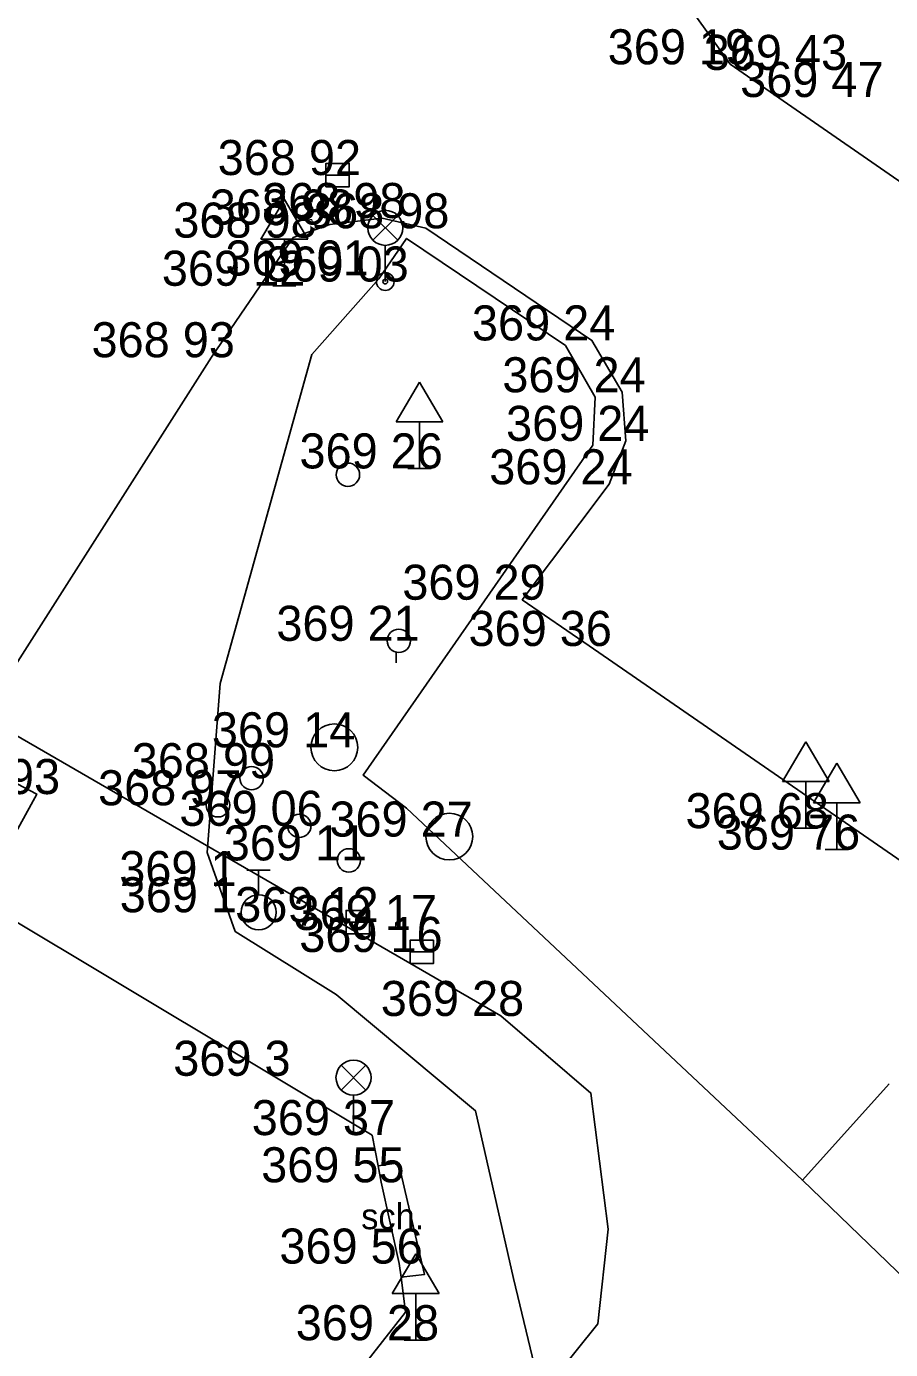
# Model space of a CAD drawing. Extents: x -688316 to -688024, y -973785 to -973591.
# Drawn here: x -688108.72 to -688090.23, y -973719.16 to -973690.84 of the extents above; entities that cross this region are included whole.
import ezdxf

# ---------------------------------------------------------------- set-up
doc = ezdxf.new("R2010")
doc.units = 0
for name, color, linetype in [('KAM_HELP', 7, 'Continuous'), ('Vrstva 10', 7, 'Continuous'), ('Vrstva 11', 7, 'Continuous'), ('Vrstva 27', 7, 'Continuous'), ('Vrstva 28_Verejne osvetleni', 7, 'Continuous'), ('Vrstva 3', 7, 'Continuous'), ('Vrstva 31', 7, 'Continuous'), ('Vrstva 33', 7, 'Continuous'), ('Vrstva 34', 7, 'Continuous'), ('Vrstva 41', 7, 'Continuous'), ('Vrstva 5', 7, 'Continuous'), ('Vrstva 6', 7, 'Continuous')]:
    doc.layers.add(name, color=color, linetype=linetype)

# ---------------------------------------------------------------- blocks, each defined once
blk = doc.blocks.new('DZ')
at = {"layer": 'Vrstva 34'}
for p, q in [((-5, 10), (0, 18.5)), ((0, 18.5), (5, 10)), ((-5, 10), (5, 10)), ((0, 0), (0, 10)), ((-2.49, 0), (2.49, 0))]:
    blk.add_line(p, q, dxfattribs=at)
blk = doc.blocks.new('SAK')
at = {"layer": 'Vrstva 27'}
blk.add_circle((0, 0), 5, dxfattribs=at)
blk = doc.blocks.new('VP')
at = {"layer": 'Vrstva 27'}
blk.add_line((-2.5, 0), (2.5, 0), dxfattribs=at)
blk.add_lwpolyline([(-2.5, -2.5), (2.5, -2.5), (2.5, 2.5), (-2.5, 2.5)], close=True, dxfattribs=at)
blk = doc.blocks.new('SV')
at = {"layer": 'Vrstva 28_Verejne osvetleni'}
blk.add_circle((0, 0), 2.5, dxfattribs=at)
blk = doc.blocks.new('SP')
at = {"layer": 'Vrstva 31'}
blk.add_circle((0, 0), 2.5, dxfattribs=at)
blk = doc.blocks.new('LA')
at = {"layer": 'Vrstva 33'}
for p, q in [((-2.65, 14.15), (2.65, 8.85)), ((-2.65, 8.85), (2.65, 14.15)), ((0, 0), (0, 7.75))]:
    blk.add_line(p, q, dxfattribs=at)
for centre, radius in [((0, 11.5), 3.75), ((0, 0), 1.9), ((0, 0), 0.5)]:
    blk.add_circle(centre, radius, dxfattribs=at)
blk = doc.blocks.new('HYN')
at = {"layer": 'Vrstva 28_Verejne osvetleni'}
for p, q in [((-2.5, 8.99), (2.5, 8.99)), ((0, 3.75), (0, 8.99))]:
    blk.add_line(p, q, dxfattribs=at)
blk.add_circle((0, 0), 3.75, dxfattribs=at)
blk = doc.blocks.new('LAO')
at = {"layer": 'Vrstva 33'}
for p, q in [((-2.65, 14.16), (2.65, 8.85)), ((-2.65, 8.85), (2.65, 14.16)), ((0, 0), (0, 7.75))]:
    blk.add_line(p, q, dxfattribs=at)
blk.add_circle((0, 11.5), 3.75, dxfattribs=at)
blk = doc.blocks.new('SKSCH0')
at = {"layer": 'Vrstva 41'}
blk.add_text('sch.', height=5.5, dxfattribs=at).set_placement((-8.15, -3.04))

msp = doc.modelspace()

# ---------------------------------------------------------------- linework, layer by layer
at = {"layer": 'KAM_HELP'}
msp.add_line((-688100.804, -973704.239), (-688100.804, -973704.461), dxfattribs=at)
at = {"layer": 'Vrstva 10'}
for p, q in [((-688093.66, -973691.65), (-688072.24, -973706.48)), ((-688103.01, -973695.36), (-688104.76, -973697.92)), ((-688104.76, -973697.92), (-688109.65, -973705.6)), ((-688077.23, -973717.52), (-688096.68, -973704.1)), ((-688098.57, -973712.02), (-688109.65, -973705.6)), ((-688117.48, -973744.56), (-688096.49, -973718.61))]:
    msp.add_line(p, q, dxfattribs=at)
for points in [[(-688093.66, -973691.65), (-688094.86, -973689.96), (-688094.89, -973687.94), (-688093.92, -973685.52), (-688092.54, -973682.87)], [(-688103.01, -973695.36), (-688102.23, -973695.08), (-688101.11, -973694.94), (-688100.17, -973695.16), (-688096.62, -973697.56), (-688095.97, -973698.67), (-688095.89, -973699.71), (-688096.25, -973700.64), (-688098.11, -973703.11), (-688096.68, -973704.1)], [(-688109.87, -973706.55), (-688108.5, -973707.27), (-688108.98, -973708.16), (-688110.34, -973707.43), (-688109.87, -973706.55)], [(-688096.49, -973718.61), (-688096.27, -973716.58), (-688096.64, -973713.67), (-688098.57, -973712.02)]]:
    msp.add_lwpolyline(points, dxfattribs=at)
at = {"layer": 'Vrstva 11'}
msp.add_lwpolyline([(-688101.19, -973715.23), (-688100.76, -973715.16), (-688100.2, -973717.55), (-688100.7, -973717.61)], dxfattribs=at)
at = {"layer": 'Vrstva 3'}
for points in [[(-688092.114, -973715.537), (-688100.586, -973707.573), (-688101.51, -973706.867), (-688096.596, -973699.801), (-688096.549, -973698.771), (-688097.183, -973697.669), (-688100.586, -973695.375), (-688101.18, -973696.24)], [(-688092.114, -973715.537), (-688100.586, -973707.573), (-688101.51, -973706.867), (-688096.596, -973699.801), (-688096.549, -973698.771), (-688097.183, -973697.669), (-688100.586, -973695.375), (-688101.18, -973696.24)], [(-688092.114, -973715.537), (-688100.586, -973707.573), (-688101.51, -973706.867), (-688096.596, -973699.801), (-688096.549, -973698.771), (-688097.183, -973697.669), (-688100.586, -973695.375), (-688101.18, -973696.24)], [(-688092.114, -973715.537), (-688100.586, -973707.573), (-688101.51, -973706.867), (-688096.596, -973699.801), (-688096.549, -973698.771), (-688097.183, -973697.669), (-688100.586, -973695.375), (-688101.18, -973696.24)], [(-688102.09, -973711.56), (-688104.25, -973710.21), (-688104.85, -973708.52), (-688104.57, -973704.9), (-688102.61, -973697.86), (-688101.18, -973696.24)], [(-688102.09, -973711.56), (-688104.25, -973710.21), (-688104.85, -973708.52), (-688104.57, -973704.9), (-688102.61, -973697.86), (-688101.18, -973696.24)], [(-688102.09, -973711.56), (-688104.25, -973710.21), (-688104.85, -973708.52), (-688104.57, -973704.9), (-688102.61, -973697.86), (-688101.18, -973696.24)], [(-688102.09, -973711.56), (-688104.25, -973710.21), (-688104.85, -973708.52), (-688104.57, -973704.9), (-688102.61, -973697.86), (-688101.18, -973696.24)], [(-688094.03, -973728.25), (-688096.82, -973723.78), (-688098.3, -973717.64), (-688099.11, -973714.05), (-688102.09, -973711.56)], [(-688094.03, -973728.25), (-688096.82, -973723.78), (-688098.3, -973717.64), (-688099.11, -973714.05), (-688102.09, -973711.56)], [(-688094.03, -973728.25), (-688096.82, -973723.78), (-688098.3, -973717.64), (-688099.11, -973714.05), (-688102.09, -973711.56)], [(-688094.03, -973728.25), (-688096.82, -973723.78), (-688098.3, -973717.64), (-688099.11, -973714.05), (-688102.09, -973711.56)], [(-688071.97, -973725.53), (-688075.592, -973732.953), (-688087.068, -973720.398), (-688092.114, -973715.537), (-688090.26, -973713.47)], [(-688071.97, -973725.53), (-688075.592, -973732.953), (-688087.068, -973720.398), (-688092.114, -973715.537), (-688090.26, -973713.47)], [(-688071.97, -973725.53), (-688075.592, -973732.953), (-688087.068, -973720.398), (-688092.114, -973715.537), (-688090.26, -973713.47)], [(-688071.97, -973725.53), (-688075.592, -973732.953), (-688087.068, -973720.398), (-688092.114, -973715.537), (-688090.26, -973713.47)]]:
    msp.add_lwpolyline(points, dxfattribs=at)
at = {"layer": 'Vrstva 5'}
msp.add_line((-688101.32, -973714.57), (-688115.6, -973706.01), dxfattribs=at)
for points in [[(-688101.32, -973714.57), (-688101.19, -973715.23), (-688101.13, -973715.58)], [(-688100.74, -973717.32), (-688100.7, -973717.61), (-688100.61, -973718.36), (-688104.1, -973722.82), (-688104.28, -973723.02), (-688104.45, -973723.22), (-688117.23, -973738.61)]]:
    msp.add_lwpolyline(points, dxfattribs=at)
at = {"layer": 'Vrstva 6'}
msp.add_line((-688101.13, -973715.58), (-688100.74, -973717.32), dxfattribs=at)

# ---------------------------------------------------------------- block references
at = {"layer": 'Vrstva 27', "xscale": 0.1, "yscale": 0.10000000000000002}
for name, p in [('VP', (-688102.06, -973694.02)), ('SAK', (-688102.13, -973706.27)), ('SAK', (-688099.67, -973708.18)), ('VP', (-688101.63, -973710.01)), ('VP', (-688100.26, -973710.65))]:
    msp.add_blockref(name, p, dxfattribs=at)
at = {"layer": 'Vrstva 28_Verejne osvetleni', "xscale": 0.1, "yscale": 0.10000000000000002}
for name, p in [('SV', (-688103.9, -973706.93)), ('SV', (-688104.62, -973707.51)), ('SV', (-688102.88, -973707.95)), ('SV', (-688101.82, -973708.69)), ('HYN', (-688103.75, -973709.8))]:
    msp.add_blockref(name, p, dxfattribs=at)
at = {"layer": 'Vrstva 31', "xscale": 0.1, "yscale": 0.10000000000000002}
for p in [(-688101.84, -973700.435), (-688100.75, -973703.99)]:
    msp.add_blockref('SP', p, dxfattribs=at)
at = {"layer": 'Vrstva 33', "xscale": 0.1, "yscale": 0.10000000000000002}
for name, p in [('LA', (-688101.04, -973696.3)), ('LAO', (-688101.72, -973714.49))]:
    msp.add_blockref(name, p, dxfattribs=at)
at = {"layer": 'Vrstva 34', "xscale": 0.1, "yscale": 0.10000000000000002}
for p in [(-688103.2, -973696.39), (-688103.2, -973696.39), (-688103.2, -973696.39), (-688103.2, -973696.39), (-688100.31, -973700.3), (-688100.31, -973700.3), (-688100.31, -973700.3), (-688100.31, -973700.3), (-688092.04, -973708), (-688092.04, -973708), (-688092.04, -973708), (-688092.04, -973708), (-688091.38, -973708.46), (-688091.38, -973708.46), (-688091.38, -973708.46), (-688091.38, -973708.46), (-688100.39, -973718.96), (-688100.39, -973718.96), (-688100.39, -973718.96), (-688100.39, -973718.96)]:
    msp.add_blockref('DZ', p, dxfattribs=at)
at = {"layer": 'Vrstva 41', "xscale": 0.1, "yscale": 0.10000000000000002}
msp.add_blockref('SKSCH0', (-688100.74, -973716.28), dxfattribs=at)

# ---------------------------------------------------------------- texts
at = {"layer": 'Vrstva 3'}
for s, p in [('369 19 ', (-688096.281, -973691.65)), ('369 19 ', (-688096.281, -973691.65)), ('369 19 ', (-688096.281, -973691.65)), ('369 19 ', (-688096.281, -973691.65)), ('369 19 ', (-688096.281, -973691.65)), ('369 19 ', (-688096.281, -973691.65)), ('369 19 ', (-688096.281, -973691.65)), ('369 43 ', (-688094.226, -973691.77)), ('369 43 ', (-688094.226, -973691.77)), ('369 43 ', (-688094.226, -973691.77)), ('369 43 ', (-688094.226, -973691.77)), ('369 43 ', (-688094.226, -973691.77)), ('369 43 ', (-688094.226, -973691.77)), ('369 43 ', (-688094.226, -973691.77)), ('369 47 ', (-688093.446, -973692.35)), ('369 47 ', (-688093.446, -973692.35)), ('369 47 ', (-688093.446, -973692.35)), ('369 47 ', (-688093.446, -973692.35)), ('369 47 ', (-688093.446, -973692.35)), ('369 47 ', (-688093.446, -973692.35)), ('369 47 ', (-688093.446, -973692.35)), ('368 92 ', (-688104.626, -973694.02)), ('368 92 ', (-688104.626, -973694.02)), ('368 92 ', (-688104.626, -973694.02)), ('368 92 ', (-688104.626, -973694.02)), ('368 92 ', (-688104.626, -973694.02)), ('368 92 ', (-688104.626, -973694.02)), ('368 92 ', (-688104.626, -973694.02)), ('368 98 ', (-688103.676, -973694.94)), ('368 98 ', (-688103.676, -973694.94)), ('368 98 ', (-688103.676, -973694.94)), ('368 98 ', (-688103.676, -973694.94)), ('368 98 ', (-688103.676, -973694.94)), ('368 98 ', (-688103.676, -973694.94)), ('368 98 ', (-688103.676, -973694.94)), ('368 98 ', (-688104.796, -973695.08)), ('368 98 ', (-688104.796, -973695.08)), ('368 98 ', (-688104.796, -973695.08)), ('368 98 ', (-688104.796, -973695.08)), ('368 98 ', (-688104.796, -973695.08)), ('368 98 ', (-688104.796, -973695.08)), ('368 98 ', (-688104.796, -973695.08)), ('368 98 ', (-688102.736, -973695.16)), ('368 98 ', (-688102.736, -973695.16)), ('368 98 ', (-688102.736, -973695.16)), ('368 98 ', (-688102.736, -973695.16)), ('368 98 ', (-688102.736, -973695.16)), ('368 98 ', (-688102.736, -973695.16)), ('368 98 ', (-688102.736, -973695.16)), ('368 98 ', (-688105.576, -973695.36)), ('368 98 ', (-688105.576, -973695.36)), ('368 98 ', (-688105.576, -973695.36)), ('368 98 ', (-688105.576, -973695.36)), ('368 98 ', (-688105.576, -973695.36)), ('368 98 ', (-688105.576, -973695.36)), ('368 98 ', (-688105.576, -973695.36)), ('369 12 ', (-688105.821, -973696.39)), ('369 12 ', (-688105.821, -973696.39)), ('369 12 ', (-688105.821, -973696.39)), ('369 12 ', (-688105.821, -973696.39)), ('369 12 ', (-688105.821, -973696.39)), ('369 12 ', (-688105.821, -973696.39)), ('369 12 ', (-688105.821, -973696.39)), ('369 01 ', (-688104.461, -973696.17)), ('369 01 ', (-688104.461, -973696.17)), ('369 01 ', (-688104.461, -973696.17)), ('369 01 ', (-688104.461, -973696.17)), ('369 01 ', (-688104.461, -973696.17)), ('369 01 ', (-688104.461, -973696.17)), ('369 01 ', (-688104.461, -973696.17)), ('369 03 ', (-688103.606, -973696.3)), ('369 03 ', (-688103.606, -973696.3)), ('369 03 ', (-688103.606, -973696.3)), ('369 03 ', (-688103.606, -973696.3)), ('369 03 ', (-688103.606, -973696.3)), ('369 03 ', (-688103.606, -973696.3)), ('369 03 ', (-688103.606, -973696.3)), ('369 24 ', (-688099.186, -973697.56)), ('369 24 ', (-688099.186, -973697.56)), ('369 24 ', (-688099.186, -973697.56)), ('369 24 ', (-688099.186, -973697.56)), ('369 24 ', (-688099.186, -973697.56)), ('369 24 ', (-688099.186, -973697.56)), ('369 24 ', (-688099.186, -973697.56)), ('368 93 ', (-688107.326, -973697.92)), ('368 93 ', (-688107.326, -973697.92)), ('368 93 ', (-688107.326, -973697.92)), ('368 93 ', (-688107.326, -973697.92)), ('368 93 ', (-688107.326, -973697.92)), ('368 93 ', (-688107.326, -973697.92)), ('368 93 ', (-688107.326, -973697.92)), ('369 24 ', (-688098.536, -973698.67)), ('369 24 ', (-688098.536, -973698.67)), ('369 24 ', (-688098.536, -973698.67)), ('369 24 ', (-688098.536, -973698.67)), ('369 24 ', (-688098.536, -973698.67)), ('369 24 ', (-688098.536, -973698.67)), ('369 24 ', (-688098.536, -973698.67)), ('369 24 ', (-688098.456, -973699.71)), ('369 24 ', (-688098.456, -973699.71)), ('369 24 ', (-688098.456, -973699.71)), ('369 24 ', (-688098.456, -973699.71)), ('369 24 ', (-688098.456, -973699.71)), ('369 24 ', (-688098.456, -973699.71)), ('369 24 ', (-688098.456, -973699.71)), ('369 26 ', (-688102.876, -973700.3)), ('369 26 ', (-688102.876, -973700.3)), ('369 26 ', (-688102.876, -973700.3)), ('369 26 ', (-688102.876, -973700.3)), ('369 26 ', (-688102.876, -973700.3)), ('369 26 ', (-688102.876, -973700.3)), ('369 26 ', (-688102.876, -973700.3)), ('369 24 ', (-688098.816, -973700.64)), ('369 24 ', (-688098.816, -973700.64)), ('369 24 ', (-688098.816, -973700.64)), ('369 24 ', (-688098.816, -973700.64)), ('369 24 ', (-688098.816, -973700.64)), ('369 24 ', (-688098.816, -973700.64)), ('369 24 ', (-688098.816, -973700.64)), ('369 29 ', (-688100.676, -973703.11)), ('369 29 ', (-688100.676, -973703.11)), ('369 29 ', (-688100.676, -973703.11)), ('369 29 ', (-688100.676, -973703.11)), ('369 29 ', (-688100.676, -973703.11)), ('369 29 ', (-688100.676, -973703.11)), ('369 29 ', (-688100.676, -973703.11)), ('369 21 ', (-688103.371, -973703.99)), ('369 21 ', (-688103.371, -973703.99)), ('369 21 ', (-688103.371, -973703.99)), ('369 21 ', (-688103.371, -973703.99)), ('369 21 ', (-688103.371, -973703.99)), ('369 21 ', (-688103.371, -973703.99)), ('369 21 ', (-688103.371, -973703.99)), ('369 36 ', (-688099.258, -973704.1)), ('369 36 ', (-688099.258, -973704.1)), ('369 36 ', (-688099.258, -973704.1)), ('369 36 ', (-688099.258, -973704.1)), ('369 36 ', (-688099.258, -973704.1)), ('369 36 ', (-688099.258, -973704.1)), ('369 36 ', (-688099.258, -973704.1)), ('369 14 ', (-688104.751, -973706.27)), ('369 14 ', (-688104.751, -973706.27)), ('369 14 ', (-688104.751, -973706.27)), ('369 14 ', (-688104.751, -973706.27)), ('369 14 ', (-688104.751, -973706.27)), ('369 14 ', (-688104.751, -973706.27)), ('369 14 ', (-688104.751, -973706.27)), ('368 99 ', (-688106.466, -973706.93)), ('368 99 ', (-688106.466, -973706.93)), ('368 99 ', (-688106.466, -973706.93)), ('368 99 ', (-688106.466, -973706.93)), ('368 99 ', (-688106.466, -973706.93)), ('368 99 ', (-688106.466, -973706.93)), ('368 99 ', (-688106.466, -973706.93)), ('368 93 ', (-688111.066, -973707.27)), ('368 93 ', (-688111.066, -973707.27)), ('368 93 ', (-688111.066, -973707.27)), ('368 93 ', (-688111.066, -973707.27)), ('368 93 ', (-688111.066, -973707.27)), ('368 93 ', (-688111.066, -973707.27)), ('368 93 ', (-688111.066, -973707.27)), ('368 97 ', (-688107.186, -973707.51)), ('368 97 ', (-688107.186, -973707.51)), ('368 97 ', (-688107.186, -973707.51)), ('368 97 ', (-688107.186, -973707.51)), ('368 97 ', (-688107.186, -973707.51)), ('368 97 ', (-688107.186, -973707.51)), ('368 97 ', (-688107.186, -973707.51)), ('369 06 ', (-688105.446, -973707.95)), ('369 06 ', (-688105.446, -973707.95)), ('369 06 ', (-688105.446, -973707.95)), ('369 06 ', (-688105.446, -973707.95)), ('369 06 ', (-688105.446, -973707.95)), ('369 06 ', (-688105.446, -973707.95)), ('369 06 ', (-688105.446, -973707.95)), ('369 68 ', (-688094.615, -973708)), ('369 68 ', (-688094.615, -973708)), ('369 68 ', (-688094.615, -973708)), ('369 68 ', (-688094.615, -973708)), ('369 68 ', (-688094.615, -973708)), ('369 68 ', (-688094.615, -973708)), ('369 68 ', (-688094.615, -973708)), ('369 27 ', (-688102.236, -973708.18)), ('369 27 ', (-688102.236, -973708.18)), ('369 27 ', (-688102.236, -973708.18)), ('369 27 ', (-688102.236, -973708.18)), ('369 27 ', (-688102.236, -973708.18)), ('369 27 ', (-688102.236, -973708.18)), ('369 27 ', (-688102.236, -973708.18)), ('369 76 ', (-688093.946, -973708.46)), ('369 76 ', (-688093.946, -973708.46)), ('369 76 ', (-688093.946, -973708.46)), ('369 76 ', (-688093.946, -973708.46)), ('369 76 ', (-688093.946, -973708.46)), ('369 76 ', (-688093.946, -973708.46)), ('369 76 ', (-688093.946, -973708.46)), ('369 11 ', (-688104.497, -973708.69)), ('369 11 ', (-688104.497, -973708.69)), ('369 11 ', (-688104.497, -973708.69)), ('369 11 ', (-688104.497, -973708.69)), ('369 11 ', (-688104.497, -973708.69)), ('369 11 ', (-688104.497, -973708.69)), ('369 11 ', (-688104.497, -973708.69)), ('369 1  ', (-688106.733, -973709.24)), ('369 1  ', (-688106.733, -973709.24)), ('369 1  ', (-688106.733, -973709.24)), ('369 1  ', (-688106.733, -973709.24)), ('369 1  ', (-688106.733, -973709.24)), ('369 1  ', (-688106.733, -973709.24)), ('369 1  ', (-688106.733, -973709.24)), ('369 1  ', (-688106.723, -973709.8)), ('369 1  ', (-688106.723, -973709.8)), ('369 1  ', (-688106.723, -973709.8)), ('369 1  ', (-688106.723, -973709.8)), ('369 1  ', (-688106.723, -973709.8)), ('369 1  ', (-688106.723, -973709.8)), ('369 1  ', (-688106.723, -973709.8)), ('369 12 ', (-688104.251, -973710.01)), ('369 12 ', (-688104.251, -973710.01)), ('369 12 ', (-688104.251, -973710.01)), ('369 12 ', (-688104.251, -973710.01)), ('369 12 ', (-688104.251, -973710.01)), ('369 12 ', (-688104.251, -973710.01)), ('369 12 ', (-688104.251, -973710.01)), ('369 17 ', (-688103.001, -973710.18)), ('369 17 ', (-688103.001, -973710.18)), ('369 17 ', (-688103.001, -973710.18)), ('369 17 ', (-688103.001, -973710.18)), ('369 17 ', (-688103.001, -973710.18)), ('369 17 ', (-688103.001, -973710.18)), ('369 17 ', (-688103.001, -973710.18)), ('369 16 ', (-688102.881, -973710.65)), ('369 16 ', (-688102.881, -973710.65)), ('369 16 ', (-688102.881, -973710.65)), ('369 16 ', (-688102.881, -973710.65)), ('369 16 ', (-688102.881, -973710.65)), ('369 16 ', (-688102.881, -973710.65)), ('369 16 ', (-688102.881, -973710.65)), ('369 28 ', (-688101.136, -973712.02)), ('369 28 ', (-688101.136, -973712.02)), ('369 28 ', (-688101.136, -973712.02)), ('369 28 ', (-688101.136, -973712.02)), ('369 28 ', (-688101.136, -973712.02)), ('369 28 ', (-688101.136, -973712.02)), ('369 28 ', (-688101.136, -973712.02)), ('369 3  ', (-688105.577, -973713.3)), ('369 3  ', (-688105.577, -973713.3)), ('369 3  ', (-688105.577, -973713.3)), ('369 3  ', (-688105.577, -973713.3)), ('369 3  ', (-688105.577, -973713.3)), ('369 3  ', (-688105.577, -973713.3)), ('369 3  ', (-688105.577, -973713.3)), ('369 37 ', (-688103.898, -973714.57)), ('369 37 ', (-688103.898, -973714.57)), ('369 37 ', (-688103.898, -973714.57)), ('369 37 ', (-688103.898, -973714.57)), ('369 37 ', (-688103.898, -973714.57)), ('369 37 ', (-688103.898, -973714.57)), ('369 37 ', (-688103.898, -973714.57)), ('369 55 ', (-688103.696, -973715.58)), ('369 55 ', (-688103.696, -973715.58)), ('369 55 ', (-688103.696, -973715.58)), ('369 55 ', (-688103.696, -973715.58)), ('369 55 ', (-688103.696, -973715.58)), ('369 55 ', (-688103.696, -973715.58)), ('369 55 ', (-688103.696, -973715.58)), ('369 56 ', (-688103.306, -973717.32)), ('369 56 ', (-688103.306, -973717.32)), ('369 56 ', (-688103.306, -973717.32)), ('369 56 ', (-688103.306, -973717.32)), ('369 56 ', (-688103.306, -973717.32)), ('369 56 ', (-688103.306, -973717.32)), ('369 56 ', (-688103.306, -973717.32)), ('369 28 ', (-688102.956, -973718.96)), ('369 28 ', (-688102.956, -973718.96)), ('369 28 ', (-688102.956, -973718.96)), ('369 28 ', (-688102.956, -973718.96)), ('369 28 ', (-688102.956, -973718.96)), ('369 28 ', (-688102.956, -973718.96)), ('369 28 ', (-688102.956, -973718.96))]:
    msp.add_text(s, height=0.75, dxfattribs=at).set_placement(p)

doc.saveas('drawing.dxf')
